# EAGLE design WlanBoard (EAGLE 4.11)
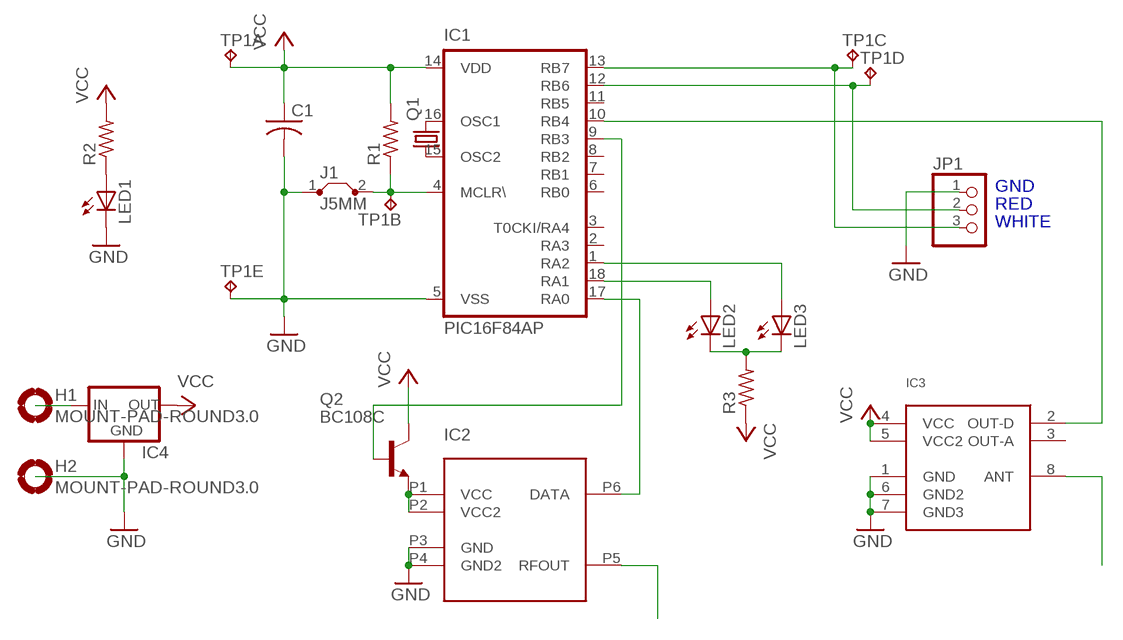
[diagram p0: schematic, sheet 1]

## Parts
C1  C-US025-025X050  [C025-025X050]
H1  MOUNT-PAD-ROUND3.0  [3,0-PAD]
H2  MOUNT-PAD-ROUND3.0  [3,0-PAD]
IC1  PIC16F84AP  [DIL18]
IC2  TX433TX433-6  [TX433-6]
IC3  RX433  [RX433-10]
IC4  78XXL  [78XXL]
J1  J5MM  [05]
JP1  PINHD-1X3  [1X03]
LED1  LED3MM  [LED3MM]
LED2  LED3MM  [LED3MM]
LED3  LED3MM  [LED3MM]
Q1  CRYTALHC18U-V  [HC18U-V]
Q2  BC108C  [TO18]
R1  R-US_0204/7  [0204/7]
R2  R-US_0204/7  [0204/7]
R3  R-US_0204/7  [0204/7]
TP1  TP5P5-25-13  [P5-25-13]

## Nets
GND: C1.2 H2.B3,0(MOUNT) IC1.5(VSS) IC2.P3(GND) IC2.P4(GND2) IC3.1(GND) IC3.6(GND2) IC3.7(GND3) IC4.GND J1.1 JP1.1 LED1.K(C) TP1.5
N$1: IC1.16(OSC1) Q1.2
N$2: IC1.15(OSC2) Q1.1
N$3: LED1.A R2.1
N$4: IC1.13(RB7) JP1.3 TP1.3
N$5: IC1.17(RA0) IC2.P6(DATA)
N$6: IC2.P5(RFOUT)
N$8: IC1.4(MCLR\) J1.2 R1.1 TP1.2
N$9: IC1.12(RB6) JP1.2 TP1.4
N$10: IC1.10(RB4) IC3.2(OUT-D)
N$11: IC3.8(ANT)
N$12: IC1.18(RA1) LED2.A
N$13: IC1.1(RA2) LED3.A
N$14: LED2.K(C) LED3.K(C) R3.2
N$17: H1.B3,0(MOUNT) IC4.IN
N$20: IC2.P1(VCC) IC2.P2(VCC2) Q2.1(E)
N$21: IC1.9(RB3) Q2.2(B)
VCC: C1.1 IC1.14(VDD) IC3.4(VCC) IC3.5(VCC2) IC4.OUT Q2.3(C) R1.2 R2.2 R3.1 TP1.1
Unconnected: IC1.2(RA3) IC1.3(T0CKI/RA4) IC1.6(RB0) IC1.7(RB1) IC1.8(RB2) IC1.11(RB5) IC3.3(OUT-A)

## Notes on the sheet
- GND
- RED
- WHITE

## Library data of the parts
C1 = rcl:C-US: CAPACITOR, American symbol
H1 H2 = holes:MOUNT-PAD-ROUND: MOUNTING PAD, round
IC1 = microchip:PIC16F8*: MICROCONTROLLER 8-Bit PIC16F8X Family - CMOS Flash/EEPROM Pin Compatible : PIC16F83, PIC16CR83, PIC16F84A, PIC16CR84 see also PIC16C*
IC2 = wireless:TX433
IC3 = wireless:RX433
IC4 = v-reg:78XXL: VOLTAGE REGULATOR
J1 = jumper:J: Bridge
JP1 = pinhead:PINHD-1X3: PIN HEADER
LED1-LED3 = led:LED: LED
Q1 = crystal:CRYTAL: CRYSTAL
Q2 = transistor-npn:BC108C: NPN Transistor
R1-R3 = rcl:R-US_: RESISTOR, American symbol
TP1 = testpad:TP5

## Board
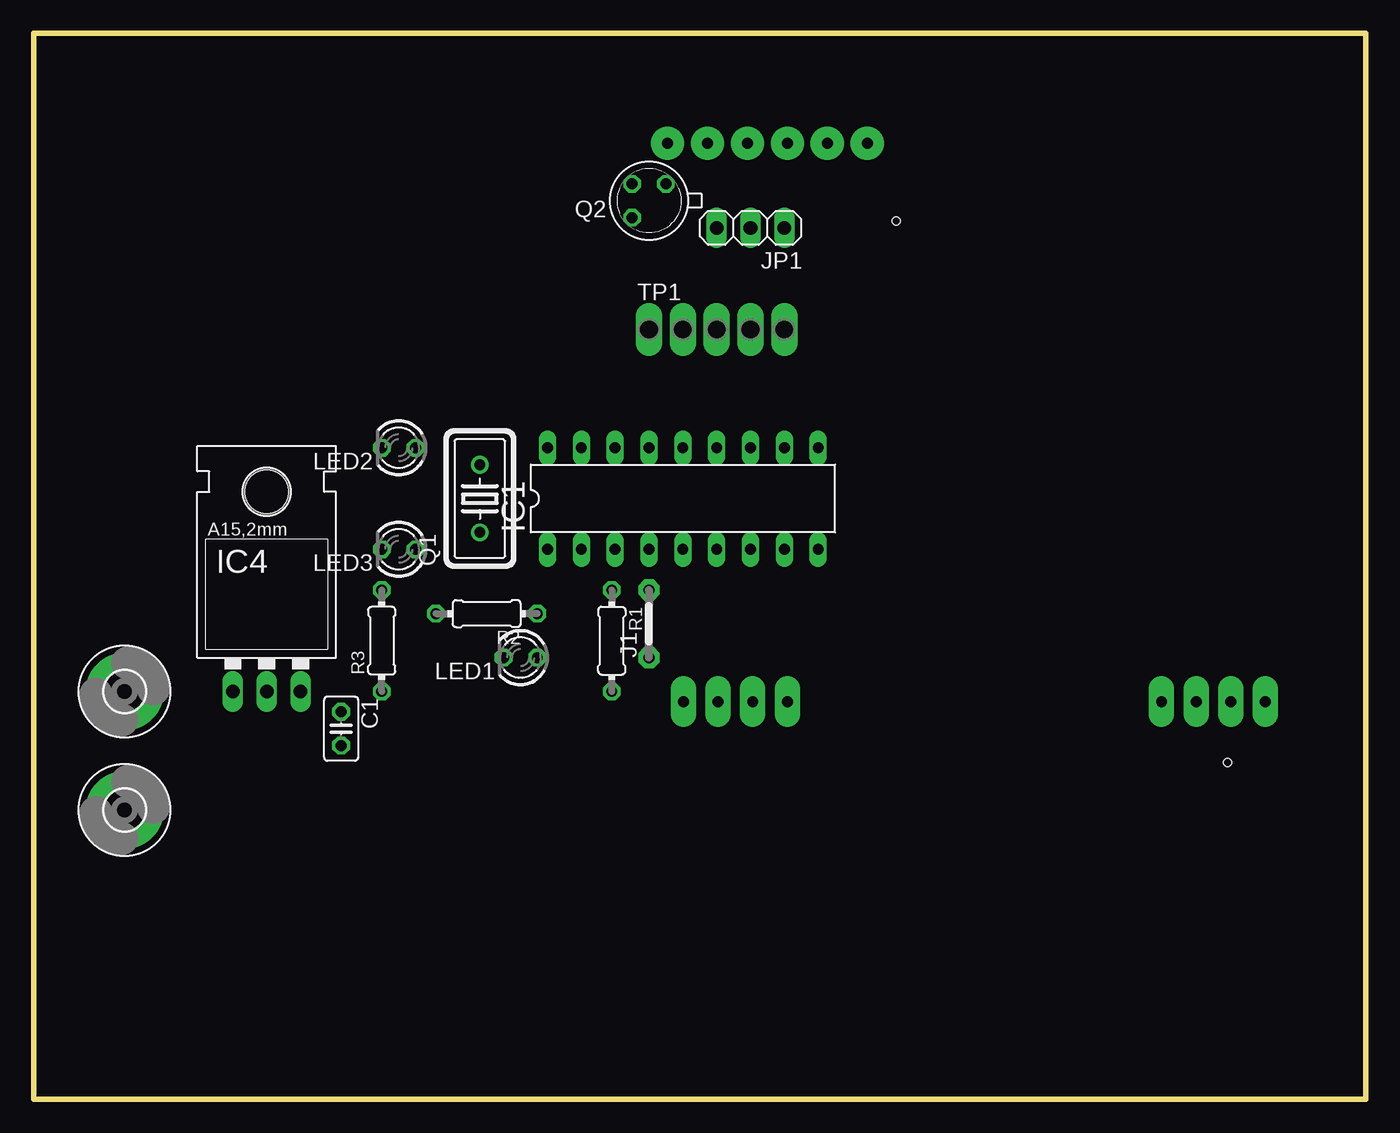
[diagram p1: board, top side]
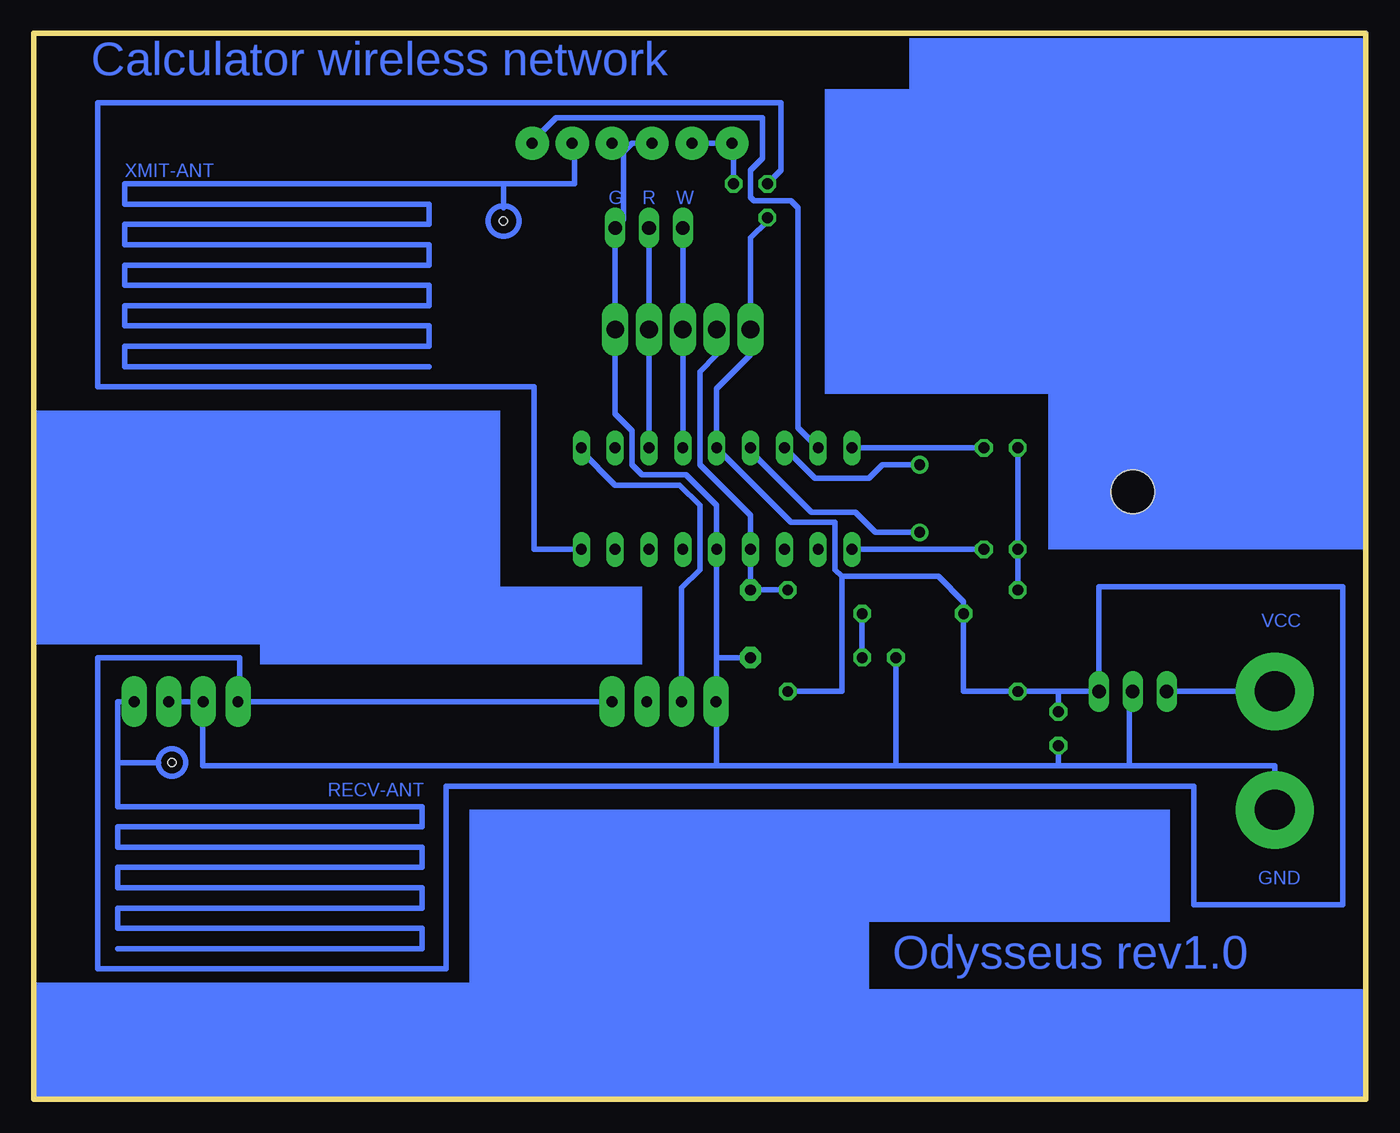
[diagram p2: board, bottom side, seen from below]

Size 100 x 80 mm. Coordinates in mm from the lower left corner, seen from the top.
Outline: 0,0 100,0 100,80 0,80 0,0
Copper layers (1*16): Top 0.035mm / dielectric 1.5mm / Bottom 0.035mm
Design rules "default": minimum track width 7mil, minimum drill 24mil, track to track 8mil, track to pad 8mil, pad to pad 8mil, via to via 8mil, smd to smd 8mil, copper to edge 40mil, drill to drill 8mil, minimum pad ring 10mil, minimum via ring 8mil, stop-mask expansion 4mil, vias tented up to drill 0mil, thermal gap 10mil
Holes 0.61 mm at 64.73,65.91 89.62,25.27

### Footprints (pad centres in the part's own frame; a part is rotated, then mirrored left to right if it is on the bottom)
C025-025X050 = drill 0.813 octagon: 1 -1.27,0; 2 1.27,0
3,0-PAD = drill 3 pad 5.842 round: B3,0 0,0
DIL18 = drill 0.813 long: 1 -10.16,-3.81; 2 -7.62,-3.81; 3 -5.08,-3.81; 4 -2.54,-3.81; 5 0,-3.81; 6 2.54,-3.81; 7 5.08,-3.81; 8 7.62,-3.81; 9 10.16,-3.81; 10 10.16,3.81; 11 7.62,3.81; 12 5.08,3.81; 13 2.54,3.81; 14 0,3.81; 15 -2.54,3.81; 16 -5.08,3.81; 17 -7.62,3.81; 18 -10.16,3.81
TX433-6 = drill 0.813 pad 2.5 round: P1 -7.5,0; P2 -4.5,0; P3 -1.5,0; P4 1.5,0; P5 4.5,0; P6 7.5,0
RX433-10 = drill 0.813 pad 1.93 long: 1 -21.8,0; 2 -19.2,0; 3 -16.6,0; 4 -14,0; 5 14.1,0; 6 16.7,0; 7 19.3,0; 8 21.9,0
78XXL = drill 1.016 long: GND 0,-3.81; IN -2.54,-3.81; OUT 2.54,-3.81 | hole 3.302: 0,11.176
05 = drill 0.813 pad 1.6 octagon: 1 -2.54,0; 2 2.54,0
1X03 = drill 1.016 long: 1 -2.54,0; 2 0,0; 3 2.54,0
LED3MM = drill 0.813 octagon: A -1.27,0; K 1.27,0
HC18U-V = drill 0.813 round: 1 -2.54,0; 2 2.54,0
TO18 = drill 0.813 octagon: 1 -1.27,-1.27; 2 1.27,-1.27; 3 1.27,1.27
0204/7 = drill 0.813 octagon: 1 -3.81,0; 2 3.81,0
P5-25-13 = drill 1.321 pad 1.905 long: 1 -5.08,0; 2 -2.54,0; 3 0,0; 4 2.54,0; 5 5.08,0

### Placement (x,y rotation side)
C1  23.08,27.81 270 top
H1  6.82,30.6 0 top
H2  6.82,21.71 0 top
IC1  48.73,45.08 0 top
IC2  55.08,71.75 0 top
IC3  70.57,29.84 0 top
IC4  17.49,34.41 0 top
J1  46.19,35.68 90 top
JP1  53.81,65.4 180 top
LED1  36.54,33.14 180 top
LED2  27.39,48.89 180 top
LED3  27.39,41.27 180 top
Q1  33.49,45.08 90 top
Q2  46.19,67.43 180 top
R1  43.4,34.41 270 top
R2  34,36.44 180 top
R3  26.12,34.41 90 top
TP1  51.27,57.78 0 top

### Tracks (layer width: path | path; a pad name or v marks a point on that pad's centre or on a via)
GND
  Bottom 0.406: 55.71,71.11 55.71,66.03 JP1.1 TP1.5 56.35,51.43 55.08,50.16 55.08,47.62 54.32,46.86 51.02,46.86 48.73,44.57 IC1.5 48.73,32.63 | IC3.7 IC3.6 87.34,29.84 87.34,25.01 48.73,25.01 | IC2.P4 56.35,71.75 55.71,71.11 | 55.71,71.11 55.08,71.75 IC2.P3 | IC4.GND 17.74,30.6 17.74,25.01 | 17.74,25.01 23.08,25.01 | 23.08,25.01 35.27,25.01 | 35.27,25.01 48.73,25.01 | 17.74,25.01 6.82,25.01 H2.B3,0 | 48.73,29.84 IC3.1 | J1.1 48.73,33.14 48.73,32.63 | 48.73,29.84 48.73,32.63 | 23.08,25.01 C1.2 | 48.73,25.01 48.73,29.84 | 35.27,25.01 LED1.K
N$1
  Bottom 0.406: Q1.2 36.28,47.62 37.3,46.6 41.36,46.6 IC1.16
N$2
  Bottom 0.406: Q1.1 36.79,42.54 38.32,44.06 41.62,44.06 46.19,48.64 IC1.15
N$3
  Bottom 0.406: LED1.A R2.1
N$4
  Bottom 0.406: IC1.13 TP1.3 JP1.3
N$5
  Bottom 0.406: IC2.P6 62.45,71.75 62.45,72 60.8,73.66 45.3,73.66 45.3,70.61 46.19,69.72 46.19,67.69 45.94,67.43 43.14,67.43 42.63,66.92 42.63,50.41 42.51,50.29 IC1.17
N$8
  Bottom 0.406: TP1.2 48.73,55.88 50,54.61 50,47.62 46.19,43.81 IC1.4 J1.2 R1.1
N$9
  Bottom 0.406: IC1.12 TP1.4 JP1.2
N$10
  Bottom 0.406: IC3.2 51.37,38.37 50,39.75 50,44.57 51.52,46.1 56.35,46.1 58.89,48.64 IC1.10
N$12
  Bottom 0.406: LED2.A IC1.18
N$13
  Bottom 0.406: LED3.A IC1.1
N$14
  Bottom 0.406: LED2.K LED3.K R3.2
N$16
  Bottom 0.406: 92.42,29.84 93.69,29.84 93.69,25.27 | 93.69,25.27 90.64,25.27 | 93.69,22.47 93.69,22.73 | 93.69,22.47 93.69,25.27 | 93.69,22.47 93.69,21.97 70.83,21.97 70.83,21.2
N$17
  Bottom 0.406: H1.B3,0 IC4.IN
N$18
  Bottom 0.406: 93.69,11.3 70.83,11.3 70.83,12.82
N$19
  Bottom 0.406: 93.69,19.68 93.69,20.44 70.83,20.44 70.83,21.97
N$20
  Bottom 0.406: 47.71,71.75 IC2.P1 | 47.71,71.75 IC2.P2 | 47.59,71.62 47.46,71.5 | 47.59,71.62 47.71,71.75 | 47.59,71.62 47.46,71.75 Q2.1
N$21
  Bottom 0.406: IC1.9 62.45,41.27 62.45,53.46 95.21,53.46 95.21,74.8 43.9,74.8 43.9,69.72 Q2.2
N$22
  Bottom 0.406: 93.18,67.94 93.18,68.7 64.73,68.7 | 64.73,68.7 64.73,66.92 | 59.4,71.75 59.4,68.7 64.73,68.7
N$23
  Bottom 0.406: 93.18,68.7 93.18,67.18 70.32,67.18 70.32,65.91 70.32,65.65 93.18,65.65 93.18,64.89
N$24
  Bottom 0.406: 93.18,64.13 70.32,64.13 70.32,62.61 93.18,62.61 93.18,61.84
N$25
  Bottom 0.406: 93.18,65.65 93.18,64.13
N$26
  Bottom 0.406: 93.69,19.68 93.69,18.92 70.83,18.92 70.83,18.16
N$27
  Bottom 0.406: 93.18,62.61 93.18,61.08 70.32,61.08 70.32,59.56 93.18,59.56 93.18,58.03 70.32,58.03 70.32,56.51 93.18,56.51 93.18,56 | 70.32,54.99 93.18,54.99 93.18,56 | 93.18,56 93.18,55.75
N$28
  Bottom 0.406: 93.69,16.63 93.69,17.39 70.83,17.39 70.83,18.92
N$29
  Bottom 0.406: 93.69,16.63 93.69,15.87 70.83,15.87 70.83,15.11
N$30
  Bottom 0.406: 93.69,13.33 93.69,14.35 70.83,14.35 70.83,15.87
N$31
  Bottom 0.406: 93.69,14.35 93.69,12.82 70.83,12.82 70.83,12.06
VCC
  Bottom 0.406: 56.6,29.84 IC3.5 | 39.33,39.24 32.09,39.24 30.19,37.33 R2.2 30.19,30.6 R3.1 23.08,30.6 | 39.33,39.24 39.84,39.75 39.84,43.3 43.14,43.3 IC1.14 48.73,53.34 46.19,55.88 TP1.1 46.19,64.64 44.92,65.91 Q2.3 | 23.08,30.6 IC4.OUT 20.03,38.48 1.74,38.48 1.74,14.6 12.92,14.6 12.92,23.49 69.05,23.49 69.05,9.77 95.21,9.77 95.21,33.14 84.54,33.14 84.54,29.84 56.6,29.84 | 23.08,30.6 C1.1 | 56.6,29.84 IC3.4 | 39.33,39.24 39.33,30.6 R1.2
(copper drawn outside any net)
  shapes: Bottom area x14, Bottom circle x2

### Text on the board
Bottom: Calculator wireless network | XMIT-ANT | W | R | G | VCC | RECV-ANT | GND | Odysseus rev1.0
